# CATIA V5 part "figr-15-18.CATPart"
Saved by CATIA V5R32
Part number: Part1
Bounding box of the stored display mesh (mm): x -46.56 to 46.56, y -38.965 to 25.965, z 0 to 40
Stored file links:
  D:\PROJECTS\Project 2022\CATIA V5 6R 2022\Resources\Part Files\c15_catia_v5_6r2022_prt\figr-15-18.CATPart
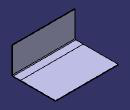
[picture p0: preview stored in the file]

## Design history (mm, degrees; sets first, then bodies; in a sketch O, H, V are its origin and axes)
SheetMetalParameters1: Thickness 1, BendRadius 1, KFactor 0.325257 {= log(min(100,max(20*SheetMetalParameters1.BendRadius,SheetMetalParameters1.Thickness)/SheetMetalParameters1.Thickness))/log(100)/2}, ReliefRadialLength 1, ReliefAxialLength 2, MinimumBendRadius 0
Body1 (main body)
  Sketch1 on xy-plane, origin (0, 0, 0), H (1, 0, 0), V (0, 1, 0)
    line L1 (-46.5596, 25.9646) -> (46.5596, 25.9646)
    line L2 (46.5596, 25.9646) -> (46.5596, -25.9646)
    line L3 (46.5596, -25.9646) -> (-46.5596, -25.9646)
    line L4 (-46.5596, -25.9646) -> (-46.5596, 25.9646)
    horizontal: L1 H, L3 H
    vertical: L2 V, L4 V
    symmetry: L1 L3 H, L4 L2 V
  Wall1: Thickness 1, Profile Sketch1
  d_NewWallOnEdge1: NewWallOnEdge_Edge edge [face of Wall1 | face of Wall1], NewWallOnEdge_Length 40, NewWallOnEdge_HeightLimitOffset 0, NewWallOnEdge_WidthOffset1 0, NewWallOnEdge_WidthOffset2 0, NewWallOnEdge_Angle 90, NewWallOnEdge_BendRadiusValue 1 {= SheetMetalParameters1.BendRadius}, NewWallOnEdge_BendTable SheetMetalParameters1, KFacteur 0.325257 {= log(min(100,max(20*d_NewWallOnEdge1.Radius,SheetMetalParameters1.Thickness)/SheetMetalParameters1.Thickness))/log(100)/2}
